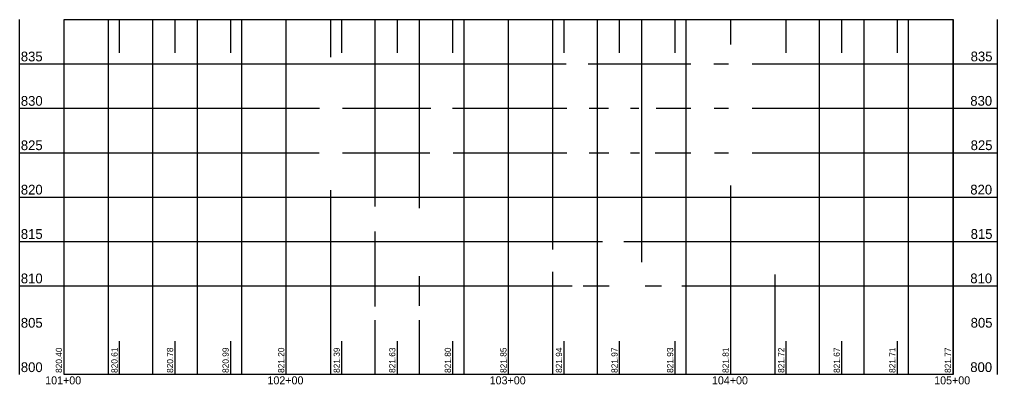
# Model space of a CAD drawing. Extents: x 1055 to 1496, y 611 to 1175.
# Drawn here: x 1055.8 to 1495.8, y 1010.9 to 1175.3 of the extents above; entities that cross this region are included whole.
import ezdxf

# ---------------------------------------------------------------- set-up
doc = ezdxf.new("R2010")
doc.units = 0
for name, color, linetype in [('Default', 7, 'Continuous'), ('GE_X_Alignment', 7, 'Continuous'), ('PF_X_Text', 7, 'Continuous'), ('SH_Major_Grid_Line', 7, 'Continuous')]:
    doc.layers.add(name, color=color, linetype=linetype)

msp = doc.modelspace()

# ---------------------------------------------------------------- linework, layer by layer
at = {"layer": 'GE_X_Alignment'}
msp.add_lwpolyline([(1075.77, 1015.32), (1075.77, 1175.32), (1475.77, 1175.32), (1475.77, 1015.32)], close=True, dxfattribs=at)
at = {"layer": 'SH_Major_Grid_Line'}
for p, q in [((1055.77, 1015.32), (1055.77, 1175.32)), ((1095.77, 1015.32), (1095.77, 1175.32)), ((1100.77, 1160.32), (1100.77, 1175.32)), ((1115.77, 1015.32), (1115.77, 1175.32)), ((1125.77, 1160.32), (1125.77, 1175.32)), ((1135.77, 1015.32), (1135.77, 1175.32)), ((1150.77, 1160.32), (1150.77, 1175.32)), ((1155.77, 1015.32), (1155.77, 1175.32)), ((1175.77, 1015.32), (1175.77, 1175.32)), ((1195.77, 1158.31), (1195.77, 1175.32)), ((1200.77, 1160.32), (1200.77, 1175.32)), ((1215.77, 1091.12), (1215.77, 1175.32)), ((1225.77, 1160.32), (1225.77, 1175.32)), ((1235.77, 1090.39), (1235.77, 1175.32)), ((1250.77, 1160.32), (1250.77, 1175.32)), ((1255.77, 1015.32), (1255.77, 1175.32)), ((1275.77, 1015.32), (1275.77, 1175.32)), ((1295.77, 1071.72), (1295.77, 1175.32)), ((1300.77, 1160.32), (1300.77, 1175.32)), ((1315.77, 1015.32), (1315.77, 1175.32)), ((1325.77, 1160.32), (1325.77, 1175.32)), ((1335.77, 1065.93), (1335.77, 1175.32)), ((1350.77, 1160.32), (1350.77, 1175.32)), ((1355.77, 1015.32), (1355.77, 1175.32)), ((1375.77, 1164.14), (1375.77, 1175.32)), ((1400.77, 1160.32), (1400.77, 1175.32)), ((1415.77, 1015.32), (1415.77, 1175.32)), ((1425.77, 1160.32), (1425.77, 1175.32)), ((1435.77, 1015.32), (1435.77, 1175.32)), ((1450.77, 1160.32), (1450.77, 1175.32)), ((1455.77, 1015.32), (1455.77, 1175.32)), ((1475.77, 1015.32), (1475.77, 1175.32)), ((1495.77, 1015.32), (1495.77, 1175.32)), ((1055.77, 1155.32), (1301.67, 1155.32)), ((1311.61, 1155.32), (1357.83, 1155.32)), ((1368.12, 1155.32), (1374.72, 1155.32)), ((1385.43, 1155.32), (1495.77, 1155.32)), ((1055.77, 1135.32), (1190.72, 1135.32)), ((1201.01, 1135.32), (1240.76, 1135.32)), ((1250.62, 1135.32), (1301.96, 1135.32)), ((1312.08, 1135.32), (1320.8, 1135.32)), ((1330.66, 1135.32), (1334.46, 1135.32)), ((1342.15, 1135.32), (1357.83, 1135.32)), ((1368.26, 1135.32), (1374.72, 1135.32)), ((1385.43, 1135.32), (1495.77, 1135.32)), ((1055.77, 1115.32), (1190.57, 1115.32)), ((1201.01, 1115.32), (1240.33, 1115.32)), ((1250.91, 1115.32), (1301.96, 1115.32)), ((1312.05, 1115.32), (1320.94, 1115.32)), ((1330.66, 1115.32), (1334.75, 1115.32)), ((1341.71, 1115.32), (1357.83, 1115.32)), ((1368.41, 1115.32), (1374.72, 1115.32)), ((1385.43, 1115.32), (1495.77, 1115.32)), ((1375.77, 1015.32), (1375.77, 1100.57)), ((1195.77, 1015.32), (1195.77, 1098.36)), ((1055.77, 1095.32), (1495.77, 1095.32)), ((1215.77, 1045.98), (1215.77, 1079.8)), ((1055.77, 1075.32), (1318.08, 1075.32)), ((1327.61, 1075.32), (1495.77, 1075.32)), ((1295.77, 1015.32), (1295.77, 1061.56)), ((1235.77, 1046.27), (1235.77, 1059.62)), ((1395.77, 1015.32), (1395.77, 1060.38)), ((1055.77, 1055.32), (1304.47, 1055.32)), ((1309.31, 1055.32), (1321.12, 1055.32)), ((1337.24, 1055.32), (1344.6, 1055.32)), ((1353.73, 1055.32), (1495.77, 1055.32)), ((1215.77, 1015.32), (1215.77, 1039.88)), ((1235.77, 1015.32), (1235.77, 1039.88)), ((1100.77, 1015.32), (1100.77, 1030.32)), ((1125.77, 1015.32), (1125.77, 1030.32)), ((1125.77, 1015.32), (1125.77, 1030.32)), ((1150.77, 1015.32), (1150.77, 1030.32)), ((1200.77, 1015.32), (1200.77, 1030.32)), ((1225.77, 1015.32), (1225.77, 1030.32)), ((1225.77, 1015.32), (1225.77, 1030.32)), ((1250.77, 1015.32), (1250.77, 1030.32)), ((1300.77, 1015.32), (1300.77, 1030.32)), ((1325.77, 1015.32), (1325.77, 1030.32)), ((1350.77, 1015.32), (1350.77, 1030.32)), ((1400.77, 1015.32), (1400.77, 1030.32)), ((1425.77, 1015.32), (1425.77, 1030.32)), ((1450.77, 1015.32), (1450.77, 1030.32))]:
    msp.add_line(p, q, dxfattribs=at)

# ---------------------------------------------------------------- texts
at = {"layer": 'Default'}
for s, height, p in [('835', 4.4, (1056.34, 1156.46)), ('835', 4.4, (1483.72, 1156.48)), ('830', 4.4, (1056.34, 1136.46)), ('830', 4.4, (1483.55, 1136.48)), ('825', 4.4, (1056.34, 1116.46)), ('825', 4.4, (1483.72, 1116.48)), ('820', 4.4, (1056.34, 1096.46)), ('820', 4.4, (1483.55, 1096.48)), ('815', 4.4, (1056.34, 1076.46)), ('815', 4.4, (1483.72, 1076.48)), ('810', 4.4, (1056.34, 1056.46)), ('810', 4.4, (1483.55, 1056.48)), ('805', 4.4, (1056.34, 1036.46)), ('805', 4.4, (1483.72, 1036.48)), ('800', 4.4, (1056.34, 1016.46)), ('800', 4.4, (1483.55, 1016.48)), ('101+00', 3.6, (1067.3, 1010.93)), ('102+00', 3.6, (1167.3, 1010.93)), ('103+00', 3.6, (1267.3, 1010.93)), ('104+00', 3.6, (1367.3, 1010.93)), ('105+00', 3.6, (1467.3, 1010.93))]:
    msp.add_text(s, height=height, dxfattribs=at).set_placement(p)
at = {"layer": 'PF_X_Text'}
for s, p in [('820.40', (1074.87, 1016.08)), ('820.61', (1099.87, 1016.08)), ('820.78', (1124.87, 1016.08)), ('820.99', (1149.87, 1016.08)), ('821.20', (1174.87, 1016.08)), ('821.39', (1199.87, 1016.08)), ('821.63', (1224.87, 1016.08)), ('821.80', (1249.87, 1016.08)), ('821.85', (1274.87, 1016.08)), ('821.94', (1299.87, 1016.08)), ('821.97', (1324.87, 1016.08)), ('821.93', (1349.87, 1016.08)), ('821.81', (1374.87, 1016.08)), ('821.72', (1399.87, 1016.08)), ('821.67', (1424.87, 1016.08)), ('821.71', (1449.87, 1016.08)), ('821.77', (1474.87, 1016.08))]:
    msp.add_text(s, height=2.8, rotation=90, dxfattribs=at).set_placement(p)

doc.saveas('drawing.dxf')
